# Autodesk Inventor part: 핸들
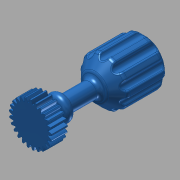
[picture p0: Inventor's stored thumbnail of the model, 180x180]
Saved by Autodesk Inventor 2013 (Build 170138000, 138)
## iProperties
Created: 2017-04
Part Number: 핸들
Material: 강철, 연강
Document SubType Name: Modeling
Designer: mduedu
Categories: <?xml version="1.0" encoding="UTF-16"?> <MemberInstance><Categories><FamilyTemplate><FamilyTemplateParameter ValueType="xs:double" Id="1" ObjectReferenceKey="da
Density: 7.86 g/cm^3
Mass: 209.327 g
Surface Area: 78.6028 cm^2
Volume: 26.6319 cm^3
CustomPartVersion: 1
Author: mduedu
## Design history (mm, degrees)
sketch "Sketch1"
  geometry: C1 r 13.5 at (0, 0)
  constraints: 1 centre point
  dimensions: "d0" = 27 diameter of C1 (= da_da)
extrude "Extrusion1" new body sketch "Sketch1" distance "d1" = 10 (= da_b); taper "d2" = 0 deg
workplane "Work Plane2"
sketch "Sketch2"
  geometry: C1 r 13.5 at (0, 0) reference; C2 r 12.5 at (0, 0)
  constraints: 1 centre point, 1 coincident
  dimensions: "d3" = 25 diameter of C2 (= da_dw)
feature "피치 지름" sketch "Sketch2" dims "d4" = 10, "d5" = 0
workplane "Work Plane8"
workplane "Work Plane9"
feature "스퍼 기어" dims "da_b" = 10, "da_d" = 25, "da_aw" = 25, "da_da" = 27, "da_df" = 22.5, "da_dw" = 25, angle "da_beta" = 0 deg, "da_lefttooth" = 0, "da_righttooth" = 0
sketch "스케치3"
  geometry: C1 r 5 at (0, 0); 1 further point
  constraints: 1 centre point, 1 coincident
  dimensions: "d49" = 10 diameter of C1
extrude "돌출2" join sketch "스케치3" distance "d50" = 60; taper "d51" = 0 deg
sketch "스케치4"
  geometry: C1 r 15 at (0, 0); 1 further point
  constraints: 1 centre point, 1 coincident
  dimensions: "d52" = 30 diameter of C1
extrude "돌출3" join sketch "스케치4" distance "d53" = 30; taper "d54" = 0 deg
chamfer "모따기1" distance "d55" = 7; stored, may be unused: second distance "d56" = 2, angle "d57" = 45 deg
sketch "스케치5"
  geometry: L1 (0, 2.2)-(0, -13.2) reference; L2 (0, -5)-(8, -5); L3 (8, -5)-(8, -11); L4 (8, -11)-(0, -11); L5 (0, -11)-(0, -5); 1 further point
  constraints: 8 end point, 2 parallel, 1 horizontal, 1 perpendicular, 1 point on line
  dimensions: "d58" = 5 distance from line of L2 point (0, 0); "d59" = 6 distance of L2.end L3.end; "d60" = 16 diameter of L3 L1
revolve "회전1" sketch "스케치5" stored, may be unused: angle "d61" = 90 deg
fillet "모깎기1" dims "d62" = 3
fillet "모깎기2" dims "d65" = 3
sketch "스케치9"
  geometry: L1 (15, -60)-(-15, -60) reference; L2 (0, -60)-(0, 0); L3 (0, -66.771)-(0, -60); A1 r 20 centre (0, -46.771) between (0, -66.771) and (15, -60)
  constraints: 4 end point, 2 point on circle, 1 centre point, 1 collinear, 1 line through centre, 1 midpoint, 1 perpendicular
  dimensions: "d84" = 20 radius of A1
revolve "회전4" sketch "스케치9" stored, may be unused: angle "d86" = 90 deg
fillet "모깎기3" dims "d72" = 3
sketch "스케치6"
  geometry: C1 r 2.5 at (0, 15); 2 further points
  constraints: 2 vertical alignment, 1 centre point, 1 other
  dimensions: "d66" = 5 diameter of C1
extrude "돌출4" cut sketch "스케치6" stored distance "d67" = 60; taper "d68" = 0 deg
fillet "모깎기4" dims "d73" = 1
node "작업 평면12"
sketch "스케치10"
  geometry: C1 r 6 at (0, 0); 1 further point
  constraints: 1 centre point, 1 coincident
  dimensions: "d87" = 12 diameter of C1
extrude "돌출5" cut sketch "스케치10" distance "d88" = 5; taper "d89" = 0 deg
fillet "모깎기5" dims "d90" = 1
body "Solid1"
pattern_circular "원형 패턴2" dims angle "d75" = 360 deg
body "Srf1"
other parameters: "d16" = 25 (= da_aw), "d17" = 0, "d34" = 1.25664 (computed from da_z), "d39" = 0, "d41" = 0, "d43" = 25 (= da_aw), "d46" = 25 (= da_aw), "d47" = 0, "d48" = 0
